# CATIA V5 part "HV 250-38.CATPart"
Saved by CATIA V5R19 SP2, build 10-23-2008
Part number: HV 250-38
Bounding box of the stored display mesh (mm): x -18.951 to 18.951, y -18.952 to 18.952, z 0.053 to 145
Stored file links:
  C:\Users\Bora\Desktop\3D KATI MODEL- CATIA PART\HV serisi\HV 250\HV 250-38.CATPart
  C:\Program Files\Dassault Systemes\B19\intel_a\reffiles\standard\MetricThickPitch.txt
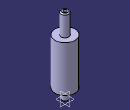
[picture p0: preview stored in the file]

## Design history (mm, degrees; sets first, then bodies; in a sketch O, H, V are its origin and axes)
Body1 (main body)
  Sketch1 on yz-plane, origin (0, 0, 0), H (0, 1, 0), V (0, 0, 1)
    point P1 (7.5, 143)
    point P3 (7.5, 143)
    point P6 (6, 17)
    point P7 (6, 1)
    point P9 (6, 1)
    point P11 (6, 17)
    line L1 (7.5, 143) -> (7.5, 106)
    arc A1 centre (5.5, 143) radius 2 from (7.5, 143) to (5.5, 145) ccw
    line L2 (6, 17) -> (6, 1)
    line L3 (5, 0) -> (6, 1)
    arc A2 centre (6, 18) radius 1 from (6, 19) to (6, 17) ccw
    line L4 (5.5, 145) -> (0, 145)
    point P12 (0, 145)
    line L5 (7.5, 106) -> (19, 106)
    line L6 (19, 106) -> (19, 19)
    line L7 (6, 19) -> (19, 19)
    line L8 (5, 0) -> (0, 0)
    coincidence: P12 V, P1 P3, P6 P11, P7 P9
    tangency: L4 A1, L7 A2
    horizontal: L5 H, L8 H
    vertical: L6 V
  Shaft1: profile Sketch1, axis Sketch1.V, angle 360
  Sketch2 on face of Shaft1 from Sketch1.L8, origin (0, 0, 0), H (1, 0, 0), V (0, -1, 0)
    point P1 (0, 0)
  Hole1: placed by Sketch2, at (0, 0, 0) direction (0, 0, 1), diameter 10.106, depth 19, threaded "M12", thread diameter 12, thread depth 19, pitch 1.75
  Sketch3 on face of Shaft1 from Sketch1.L4, origin (0, 0, 145), H (1, 0, 0), V (0, 1, 0)
    point P1 (0, 0)
  Hole2: placed by Sketch3, at (0, 0, 145) direction (0, 0, -1), diameter 6.647, depth 15, threaded "M8", thread diameter 8, thread depth 15, pitch 1.25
